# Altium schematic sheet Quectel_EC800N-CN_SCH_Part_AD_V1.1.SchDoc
size A2
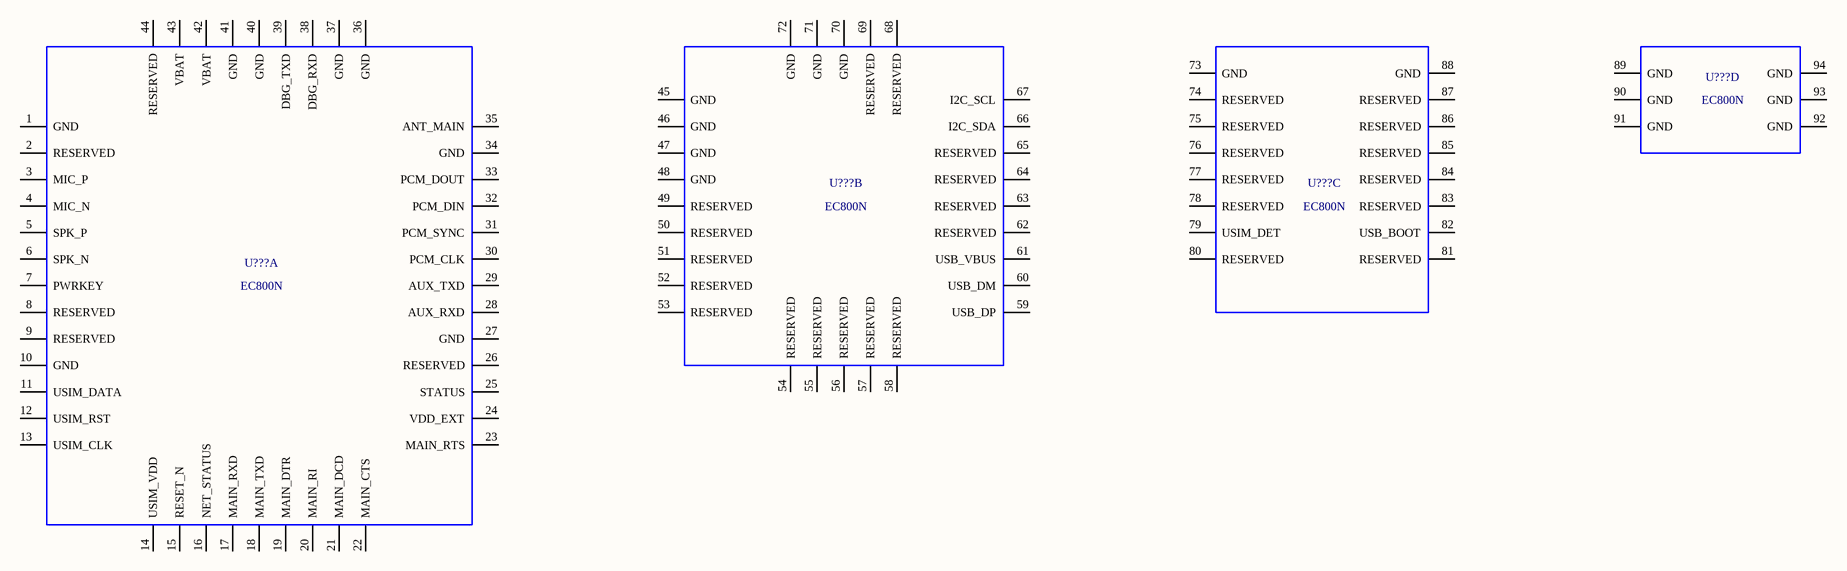
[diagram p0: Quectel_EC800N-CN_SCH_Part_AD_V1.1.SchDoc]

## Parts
(Parts that share a designator on the sheet are numbered #1, #2 ... from top to bottom, then left to right.)
U???#1  EC800N  (part D of 4)
U???#2  EC800N  (part B of 4)
U???#3  EC800N  (part C of 4)
U???#4  EC800N  (part A of 4)

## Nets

Not connected (* = marked no-connect by the designer): U???#1 89(GND) 90(GND) 91(GND) 92(GND) 93(GND) 94(GND); U???#2 45(GND) 46(GND) 47(GND) 48(GND) 49(RESERVED) 50(RESERVED) 51(RESERVED) 52(RESERVED) 53(RESERVED) 54(RESERVED) 55(RESERVED) 56(RESERVED) 57(RESERVED) 58(RESERVED) 59(USB_DP) 60(USB_DM) 61(USB_VBUS) 62(RESERVED) 63(RESERVED) 64(RESERVED) 65(RESERVED) 66(I2C_SDA) 67(I2C_SCL) 68(RESERVED) 69(RESERVED) 70(GND) 71(GND) 72(GND); U???#3 73(GND) 74(RESERVED) 75(RESERVED) 76(RESERVED) 77(RESERVED) 78(RESERVED) 79(USIM_DET) 80(RESERVED) 81(RESERVED) 82(USB_BOOT) 83(RESERVED) 84(RESERVED) 85(RESERVED) 86(RESERVED) 87(RESERVED) 88(GND); U???#4 1(GND) 2(RESERVED) 3(MIC_P) 4(MIC_N) 5(SPK_P) 6(SPK_N) 7(PWRKEY) 8(RESERVED) 9(RESERVED) 10(GND) 11(USIM_DATA) 12(USIM_RST) 13(USIM_CLK) 14(USIM_VDD) 15(RESET_N) 16(NET_STATUS) 17(MAIN_RXD) 18(MAIN_TXD) 19(MAIN_DTR) 20(MAIN_RI) 21(MAIN_DCD) 22(MAIN_CTS) 23(MAIN_RTS) 24(VDD_EXT) 25(STATUS) 26(RESERVED) 27(GND) 28(AUX_RXD) 29(AUX_TXD) 30(PCM_CLK) 31(PCM_SYNC) 32(PCM_DIN) 33(PCM_DOUT) 34(GND) 35(ANT_MAIN) 36(GND) 37(GND) 38(DBG_RXD) 39(DBG_TXD) 40(GND) 41(GND) 42(VBAT) 43(VBAT) 44(RESERVED)

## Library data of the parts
U???#1-U???#4 = EC800N: EC800N-CN Moudle 94PIN 15.8X17.7mm H2.4mm RO; Manufacturer: Quectel; Geometry.Height: 2.4mm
